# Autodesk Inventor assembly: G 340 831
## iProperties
Created: 2005-12
Part Number: G 340 831
Document SubType Name: Assembly
Designer: I.Baliuc
Manufacturer: Standard
Standards Organization: Custom
Description: Stromschiene, oben
Mass: 1640.08 g
Surface Area: 374.305 cm^2
Volume: 183.154 cm^3
Density: 8.95462 g/cm^3
Title: Stromschiene
Company: Mayer & Müller AG Schaltgeräte
Zweck: für Festeinbau
Author: T.Messerschmitt
Revision Number: 340831
